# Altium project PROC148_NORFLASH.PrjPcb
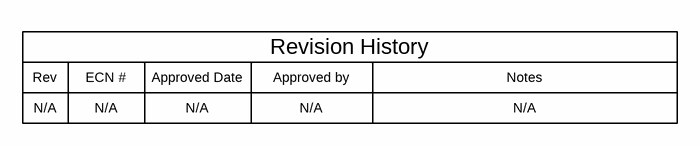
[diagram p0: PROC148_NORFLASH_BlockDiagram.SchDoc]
CopyrightYear: 2022; PCB_Layout: Brennan Hartigan; PCB_Rev: A; PRJ_Customer: Public Release; PRJ_Engineer: Brennan Hartigan; PRJ_Number: PROC148_NORFLASH; PRJ_Title: TMDSHSECDOCK NOR FLASH Board; SCH_Rev: A; TechSupport: http://www.ti.com/support; TID: N/A
3 sheets, 36 parts. Net scope: global (net labels, ports and power ports of the same name join across sheets).
Board file: PROC148_NORFLASH.PcbDoc
Sheets:
  PROC148_NORFLASH_BlockDiagram.SchDoc
  PROC148_NORFLASH.SchDoc
  PROC148_NORFLASH_Hardware.SchDoc

## Sheet PROC148_NORFLASH_BlockDiagram.SchDoc
size 431 x 279 mm; Date: Not shown in title block; ApprovedBy: Not shown in title block; CheckedBy: Not shown in title block; Author: Not shown in title block; CompanyName: Not shown in title block; Engineer: Not shown in title block; Organization: Not shown in title block; Address1: Not shown in title block; Address2: Not shown in title block; Address3: Not shown in title block; Address4: Not shown in title block; DocumentNumber: 1; Revision: Use project parameter SCH_Rev; SheetNumber: 1; SheetTotal: 3; PageSetup: Record=PageOptions¦CenterHorizontal=True¦CenterVertical=True¦PrintScale=1.00¦XCorrection=1.00¦YCorrection=1.00¦PrintKind=0¦BorderSize=5000000¦LeftOffset=0¦BottomOffset=0¦Orientation=2¦PaperLength=1000¦PaperWidth=1000¦Scale=100¦PaperSource=15¦PrintQuality=600¦MediaType=1¦DitherType=10¦PaperKind=Letter¦PrintScaleMode=1

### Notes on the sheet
- Rev
- N/A
- ECN #
- Approved Date
- Approved by
- Revision History
- Notes

## Sheet PROC148_NORFLASH.SchDoc
size 431 x 279 mm; Date: Not shown in title block; ApprovedBy: Not shown in title block; CheckedBy: Not shown in title block; Author: Not shown in title block; CompanyName: Not shown in title block; Engineer: Not shown in title block; Organization: Not shown in title block; Address1: Not shown in title block; Address2: Not shown in title block; Address3: Not shown in title block; Address4: Not shown in title block; DocumentNumber: 2; Revision: Use project parameter SCH_Rev; SheetNumber: 2; SheetTotal: 3; PageSetup: Record=PageOptions¦CenterHorizontal=True¦CenterVertical=True¦PrintScale=1.00¦XCorrection=1.00¦YCorrection=1.00¦PrintKind=0¦BorderSize=5000000¦LeftOffset=0¦BottomOffset=0¦Orientation=2¦PaperLength=1000¦PaperWidth=1000¦Scale=100¦PaperSource=15¦PrintQuality=600¦MediaType=1¦DitherType=10¦PaperKind=Letter¦PrintScaleMode=1
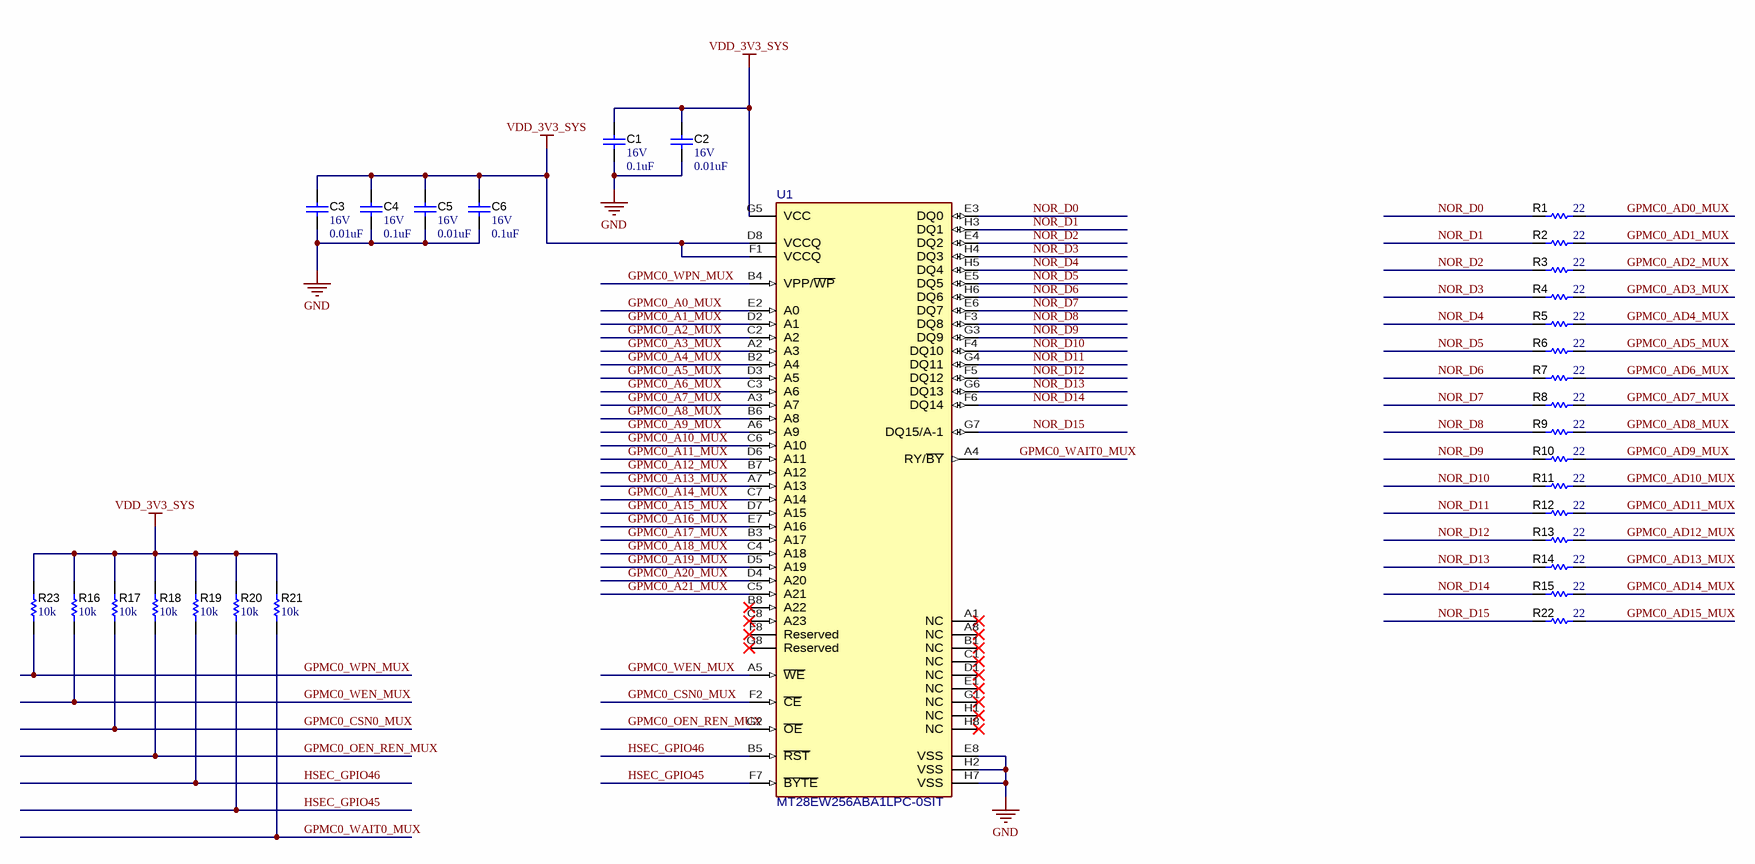
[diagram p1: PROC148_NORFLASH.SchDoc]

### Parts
C1  VDC_V: 16V  ValueDisplayed: 0.1uF  [0201_033]  (hidden comment: GRM033R61C104KE84D)
C2  VDC_V: 16V  ValueDisplayed: 0.01uF  [0201_033]  (hidden comment: GRM033R61C103KA12D)
C3  VDC_V: 16V  ValueDisplayed: 0.01uF  [0201_033]  (hidden comment: GRM033R61C103KA12D)
C4  VDC_V: 16V  ValueDisplayed: 0.1uF  [0201_033]  (hidden comment: GRM033R61C104KE84D)
C5  VDC_V: 16V  ValueDisplayed: 0.01uF  [0201_033]  (hidden comment: GRM033R61C103KA12D)
C6  VDC_V: 16V  ValueDisplayed: 0.1uF  [0201_033]  (hidden comment: GRM033R61C104KE84D)
R1  ValueDisplayed: 22  [0201]  (hidden comment: ERJ-1GNJ220C)
R2  ValueDisplayed: 22  [0201]  (hidden comment: ERJ-1GNJ220C)
R3  ValueDisplayed: 22  [0201]  (hidden comment: ERJ-1GNJ220C)
R4  ValueDisplayed: 22  [0201]  (hidden comment: ERJ-1GNJ220C)
R5  ValueDisplayed: 22  [0201]  (hidden comment: ERJ-1GNJ220C)
R6  ValueDisplayed: 22  [0201]  (hidden comment: ERJ-1GNJ220C)
R7  ValueDisplayed: 22  [0201]  (hidden comment: ERJ-1GNJ220C)
R8  ValueDisplayed: 22  [0201]  (hidden comment: ERJ-1GNJ220C)
R9  ValueDisplayed: 22  [0201]  (hidden comment: ERJ-1GNJ220C)
R10  ValueDisplayed: 22  [0201]  (hidden comment: ERJ-1GNJ220C)
R11  ValueDisplayed: 22  [0201]  (hidden comment: ERJ-1GNJ220C)
R12  ValueDisplayed: 22  [0201]  (hidden comment: ERJ-1GNJ220C)
R13  ValueDisplayed: 22  [0201]  (hidden comment: ERJ-1GNJ220C)
R14  ValueDisplayed: 22  [0201]  (hidden comment: ERJ-1GNJ220C)
R15  ValueDisplayed: 22  [0201]  (hidden comment: ERJ-1GNJ220C)
R16  ValueDisplayed: 10k  [0201]  (hidden comment: RC0201JS-7D10KL)
R17  ValueDisplayed: 10k  [0201]  (hidden comment: RC0201JS-7D10KL)
R18  ValueDisplayed: 10k  [0201]  (hidden comment: RC0201JS-7D10KL)
R19  ValueDisplayed: 10k  [0201]  (hidden comment: RC0201JS-7D10KL)
R20  ValueDisplayed: 10k  [0201]  (hidden comment: RC0201JS-7D10KL)
R21  ValueDisplayed: 10k  [0201]  (hidden comment: RC0201JS-7D10KL)
R22  ValueDisplayed: 22  [0201]  (hidden comment: ERJ-1GNJ220C)
R23  ValueDisplayed: 10k  [0201]  (hidden comment: RC0201JS-7D10KL)
U1  MT28EW256ABA1LPC-0SIT  [FP-MT28EW256ABA1LPC-0SIT_LBGA64-IPC_C]

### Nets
GND: C1.2 C2.2 C3.2 C4.2 C5.2 C6.2 U1.E8(VSS) U1.H2(VSS) U1.H7(VSS)
VDD_3V3_SYS: C1.1 C2.1 C3.1 C4.1 C5.1 C6.1 R16.2 R17.2 R18.2 R19.2 R20.2 R21.2 R23.2 U1.D8(VCCQ) U1.F1(VCCQ) U1.G5(VCC)
GPMC0_A0_MUX: U1.E2(A0)
GPMC0_A1_MUX: U1.D2(A1)
GPMC0_A2_MUX: U1.C2(A2)
GPMC0_A3_MUX: U1.A2(A3)
GPMC0_A4_MUX: U1.B2(A4)
GPMC0_A5_MUX: U1.D3(A5)
GPMC0_A6_MUX: U1.C3(A6)
GPMC0_A7_MUX: U1.A3(A7)
GPMC0_A8_MUX: U1.B6(A8)
GPMC0_A9_MUX: U1.A6(A9)
GPMC0_A10_MUX: U1.C6(A10)
GPMC0_A11_MUX: U1.D6(A11)
GPMC0_A12_MUX: U1.B7(A12)
GPMC0_A13_MUX: U1.A7(A13)
GPMC0_A14_MUX: U1.C7(A14)
GPMC0_A15_MUX: U1.D7(A15)
GPMC0_A16_MUX: U1.E7(A16)
GPMC0_A17_MUX: U1.B3(A17)
GPMC0_A18_MUX: U1.C4(A18)
GPMC0_A19_MUX: U1.D5(A19)
GPMC0_A20_MUX: U1.D4(A20)
GPMC0_A21_MUX: U1.C5(A21)
GPMC0_AD0_MUX: R1.2
GPMC0_AD1_MUX: R2.2
GPMC0_AD2_MUX: R3.2
GPMC0_AD3_MUX: R4.2
GPMC0_AD4_MUX: R5.2
GPMC0_AD5_MUX: R6.2
GPMC0_AD6_MUX: R7.2
GPMC0_AD7_MUX: R8.2
GPMC0_AD8_MUX: R9.2
GPMC0_AD9_MUX: R10.2
GPMC0_AD10_MUX: R11.2
GPMC0_AD11_MUX: R12.2
GPMC0_AD12_MUX: R13.2
GPMC0_AD13_MUX: R14.2
GPMC0_AD14_MUX: R15.2
GPMC0_AD15_MUX: R22.2
GPMC0_CSN0_MUX: R17.1 U1.F2(~{CE})
GPMC0_OEN_REN_MUX: R18.1 U1.G2(~{OE})
GPMC0_WAIT0_MUX: R21.1 U1.A4(RY/~{BY})
GPMC0_WEN_MUX: R16.1 U1.A5(~{WE})
GPMC0_WPN_MUX: R23.1 U1.B4(VPP/~{WP})
HSEC_GPIO45: R20.1 U1.F7(~{BYTE})
HSEC_GPIO46: R19.1 U1.B5(~{RST})
NOR_D0: R1.1 U1.E3(DQ0)
NOR_D1: R2.1 U1.H3(DQ1)
NOR_D2: R3.1 U1.E4(DQ2)
NOR_D3: R4.1 U1.H4(DQ3)
NOR_D4: R5.1 U1.H5(DQ4)
NOR_D5: R6.1 U1.E5(DQ5)
NOR_D6: R7.1 U1.H6(DQ6)
NOR_D7: R8.1 U1.E6(DQ7)
NOR_D8: R9.1 U1.F3(DQ8)
NOR_D9: R10.1 U1.G3(DQ9)
NOR_D10: R11.1 U1.F4(DQ10)
NOR_D11: R12.1 U1.G4(DQ11)
NOR_D12: R13.1 U1.F5(DQ12)
NOR_D13: R14.1 U1.G6(DQ13)
NOR_D14: R15.1 U1.F6(DQ14)
NOR_D15: R22.1 U1.G7(DQ15/A-1)

Not connected (* = marked no-connect by the designer): U1 A1(NC)* A8(NC)* B1(NC)* B8(A22)* C1(NC)* C8(A23)* D1(NC)* E1(NC)* F8(Reserved)* G1(NC)* G8(Reserved)* H1(NC)* H8(NC)*

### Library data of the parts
C1 C4 C6 = CMP-0009717-2: CAP, CERM, 0.1 uF, 16 V, +/- 10%, X5R, 0201; Manufacturer: MuRata; TaMin_C: -55°C; Polarized: N; SizeAreaWB_mm2: 2.08; Value1: Unknown; U/M: EA; Value: 0.1uF; TaMax_C: 85°C; SizeZ_mm: 0.33; SizeX_mm: 0.6; SizeY_mm: 0.3; Cap_Case: 0201; SizeArea_mm2: 0.18; Cap_F: 100nF; AEC Category: Q200
C2 C3 C5 = CMP-0009716-1: CAP, CERM, 0.01 uF, 16 V, +/- 10%, X5R, 0201; Manufacturer: MuRata; TaMin_C: -55°C; Polarized: N; SizeAreaWB_mm2: 2.08; Value1: Unknown; U/M: EA; Value: 0.01uF; TaMax_C: 85°C; SizeZ_mm: 0.33; SizeX_mm: 0.6; SizeY_mm: 0.3; Cap_Case: 0201; SizeArea_mm2: 0.18; Cap_F: 10nF; AEC Category: Q200
R1-R15 R22 = CMP-0027015-2: RES, 22, 5%, 0.05 W, AEC-Q200 Grade 1, 0201; Manufacturer: Panasonic; RevisionId: 1; AccessRights: 2147483647; Folder: Components\Non-TI Components\Resistors\SMT\0201\100 ohm -\5%\; ContentType: Component; Power_W: 50mW; TempCo: 200 ppm/C; Value_Code: 22R0; U/M: EA; Value: 22; EIA_Code: E24; SizeX_mm: 0.6; SizeY_mm: 0.3; SizeZ_mm: 0.26; Value2: 0.05W; SizeArea_mm2: 0.18; AEC Qualified: Y; AEC Category: Q200
R16-R21 R23 = CMP-0027260-1: RES, 10 k, 5%, 0.05 W, 0201; Manufacturer: Yageo America; Power_W: 50mW; TempCo: 200 ppm/C; Value_Code: 10k0; U/M: EA; Value: 10k; EIA_Code: E24; SizeX_mm: 0.6; SizeY_mm: 0.3; SizeZ_mm: 0.26; Value2: 0.05W; SizeArea_mm2: 0.18; AEC Qualified: N; VDC_V: 25V; AEC Category: Q200
U1 = CMP-0095868-1: FLASH - NOR Memory IC 256Mb (32M x 8, 16M x 16) Parallel 75 ns 64-LBGA (11x13); Manufacturer: Micron; Memory Type: FLASH,NOR; Standoff Height: 0.44mm; Min Supply Voltage: 1.65V; TaMin_C: -40°C; Max Supply Voltage: 3.6V; Access Time: 75ns; Memory Size: 256Mbits; SizeZ_mm: 1.4mm; AEC Qualified: No; TaMax_C: +85°C

## Sheet PROC148_NORFLASH_Hardware.SchDoc
size 431 x 279 mm; Date: Not shown in title block; ApprovedBy: Not shown in title block; CheckedBy: Not shown in title block; Author: Not shown in title block; CompanyName: Not shown in title block; Engineer: Not shown in title block; Organization: Not shown in title block; Address1: Not shown in title block; Address2: Not shown in title block; Address3: Not shown in title block; Address4: Not shown in title block; DocumentNumber: 3; Revision: Use project parameter SCH_Rev; SheetNumber: 3; SheetTotal: 3; PageSetup: Record=PageOptions¦CenterHorizontal=True¦CenterVertical=True¦PrintScale=1.00¦XCorrection=1.00¦YCorrection=1.00¦PrintKind=0¦BorderSize=5000000¦LeftOffset=0¦BottomOffset=0¦Orientation=2¦PaperLength=1000¦PaperWidth=1000¦Scale=100¦PaperSource=15¦PrintQuality=600¦MediaType=1¦DitherType=10¦PaperKind=Letter¦PrintScaleMode=1
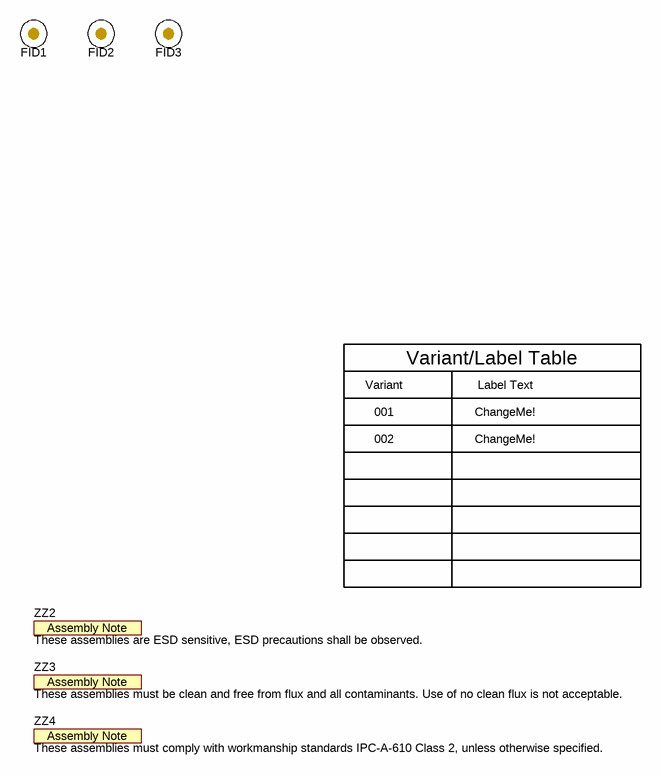
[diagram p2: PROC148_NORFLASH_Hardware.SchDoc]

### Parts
FID1  Fiducial  [Fiducial10-20]  (value not drawn)
FID2  Fiducial  [Fiducial10-20]  (value not drawn)
FID3  Fiducial  [Fiducial10-20]  (value not drawn)
ZZ2  These assemblies are ESD sensitive, ESD precautions shall be observed.  [AssemblyNote]  (no BOM)
ZZ3  These assemblies must be clean and free from flux and all contaminants. Use of no clean flux is not acceptable.  [AssemblyNote]  (no BOM)
ZZ4  These assemblies must comply with workmanship standards IPC-A-610 Class 2, unless otherwise specified.  [AssemblyNote]  (no BOM)

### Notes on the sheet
- Variant
- Variant/Label Table
- Label Text
- 001
- 002
- ChangeMe!

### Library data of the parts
FID1-FID3 = CMP-0077181-1: Fiducial mark.  There is nothing to buy or mount.
ZZ2 = CMP-0077236-1
ZZ3 = CMP-0077237-1
ZZ4 = CMP-0077238-1

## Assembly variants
001: not fitted FID1 FID2 FID3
